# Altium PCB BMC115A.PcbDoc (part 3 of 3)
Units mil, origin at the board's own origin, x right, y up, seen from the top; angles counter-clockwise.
Board outline 5500 x 3200 mil, 4 copper layers (Top Layer, Signal Layer 1, Signal Layer 2, Bottom Layer), stack 61.6 mil thick; 199 components, 81 nets, 456 pads, 1349 vias.
Unrouted connection lines stored in the file: 741.
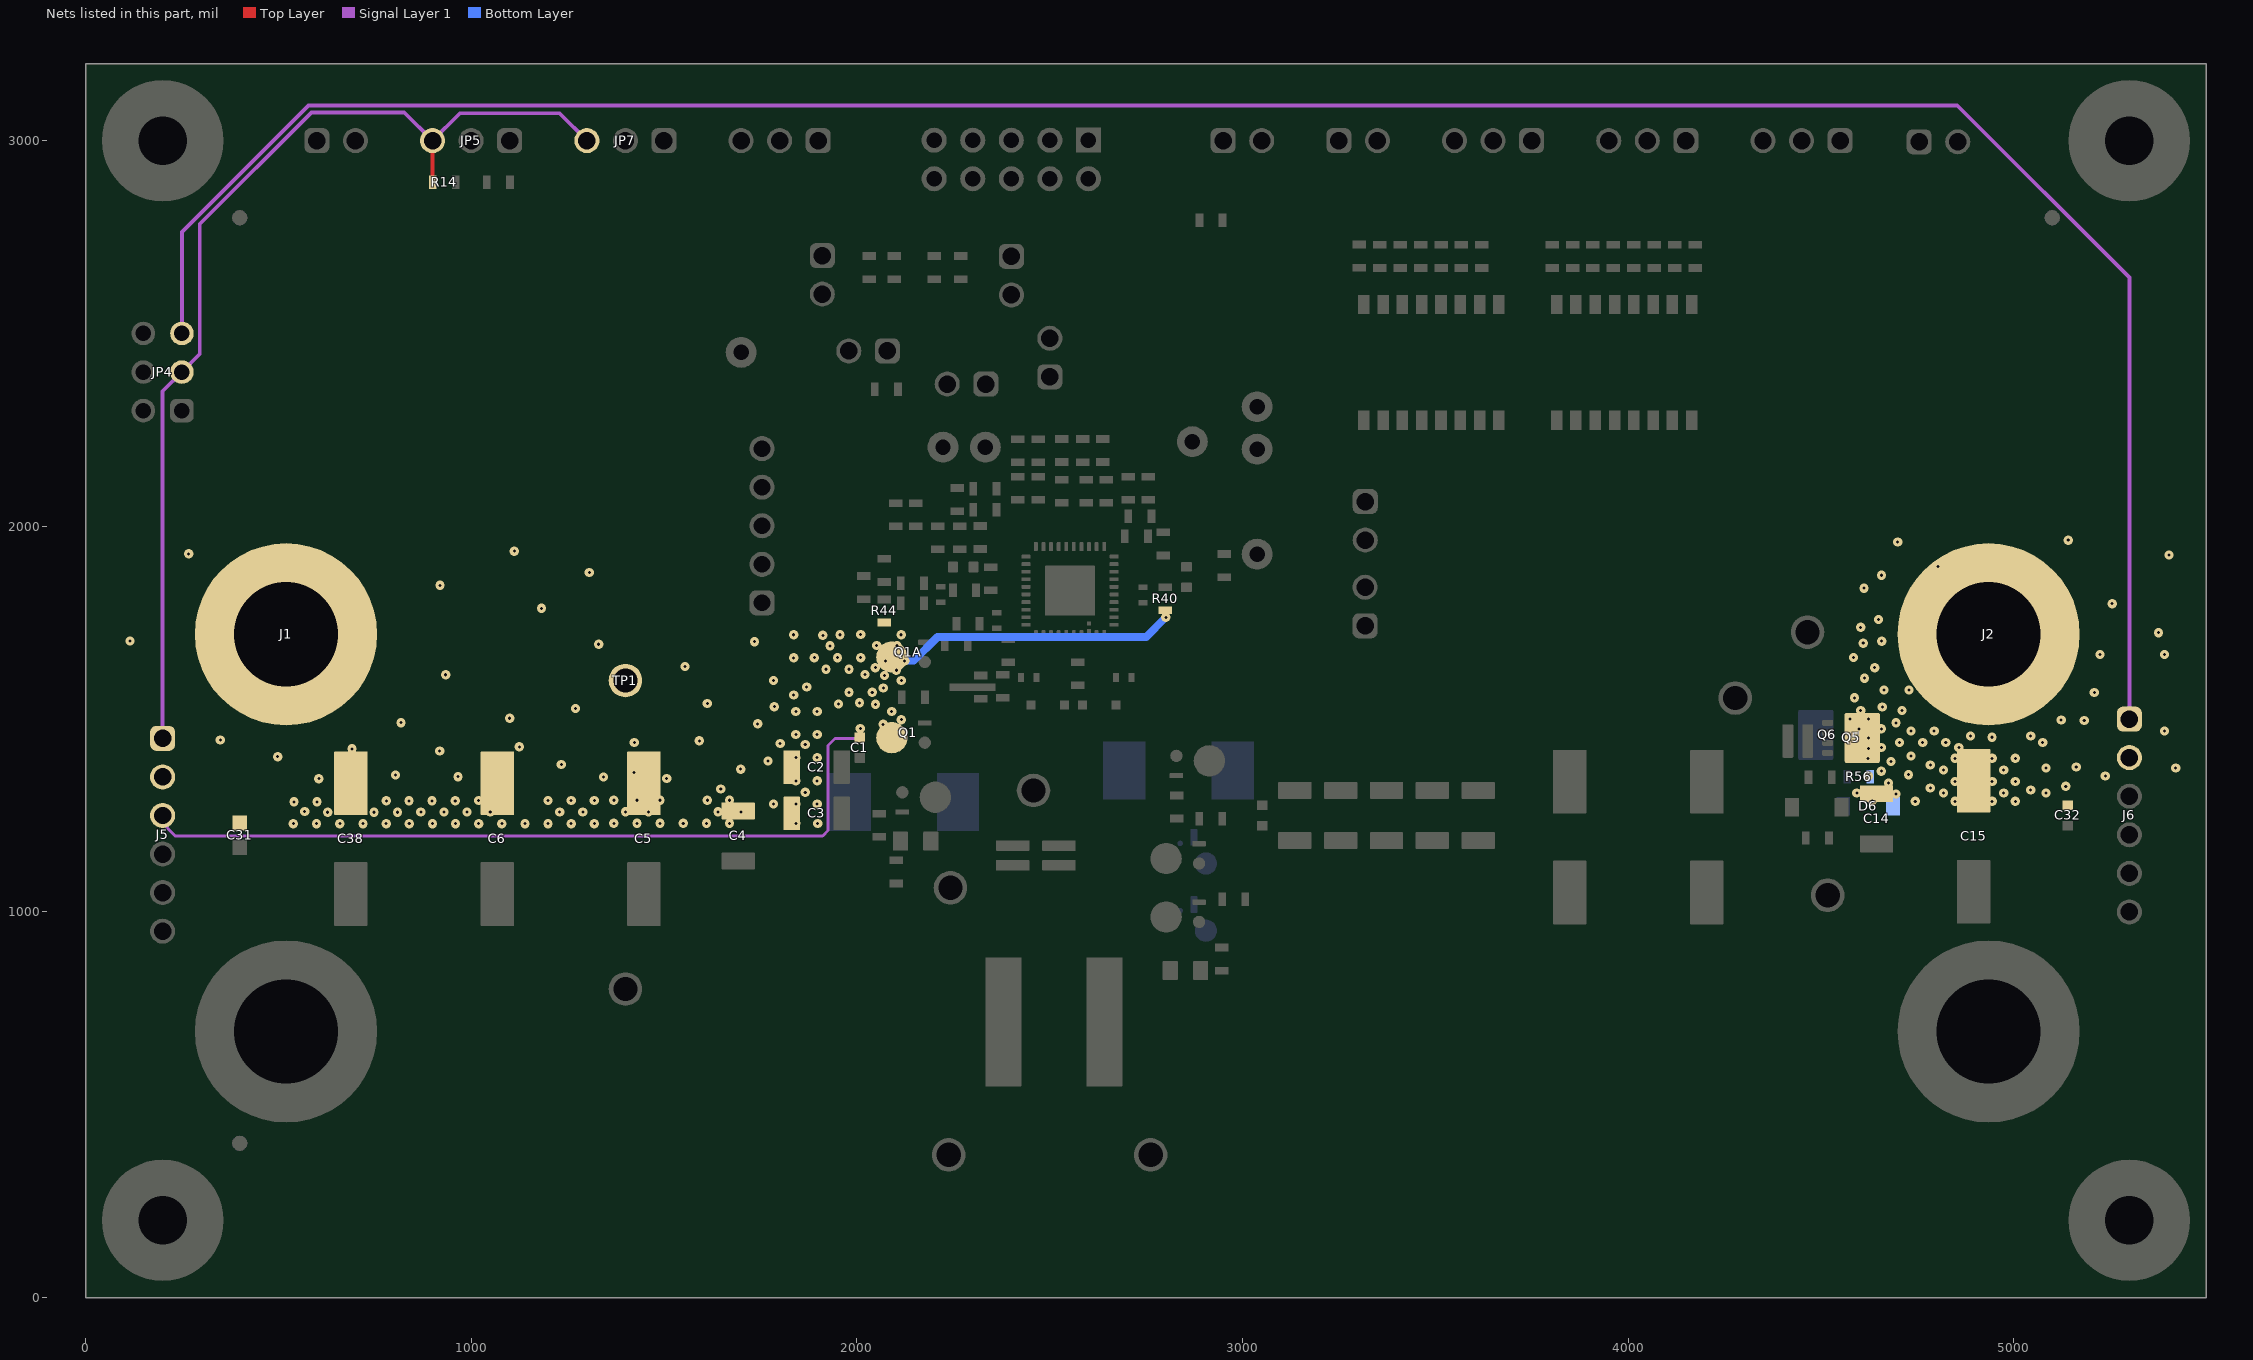
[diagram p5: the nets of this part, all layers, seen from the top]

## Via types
v1: diameter 24, hole 7.87, Top Layer to Bottom Layer, tented both sides, 1320 vias
v2: diameter 19.68, hole 7.87, Top Layer to Bottom Layer, tented both sides, 17 vias
v3: diameter 24, hole 8, Top Layer to Bottom Layer, tented both sides, 8 vias
v4: diameter 34, hole 16, Top Layer to Bottom Layer, tented both sides, 2 vias
v5: diameter 19.68, hole 7.87, Top Layer to Bottom Layer, 2 vias

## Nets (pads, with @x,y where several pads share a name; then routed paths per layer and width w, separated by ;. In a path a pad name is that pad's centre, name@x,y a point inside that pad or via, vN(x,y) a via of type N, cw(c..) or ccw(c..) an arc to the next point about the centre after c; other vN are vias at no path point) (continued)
VIN: C1.1 C2.2 C3.2 C4.2 C5.2 C6.2 C31.1 C38.2 J1.1 J5.1 J5.2 J5.3 JP4.3 JP5.3 JP7.3 Q1.5-6-7-8 Q1A.5-6-7-8 R14.2 R40.2 R44.2 TP1.1 | length 5538.3
  Top Layer w10: JP5.3@900,3005.59 JP5.3@900,3000 900,2893.04 R14.2@900.36,2892.68
  Top Layer w20: v1(2801.36,1763.92) R40.2@2801.36,1780.84
  Signal Layer 1 w8: J5.3@200,1250 210.9,1239.1 210.9,1218.72 232.76,1196.85 1911.42,1196.85 1925.49,1210.92 1925.49,1431.52 1943.54,1449.57 2000.24,1449.57 2009.24,1458.57 v1(2009.24,1475.56)
  Signal Layer 1 w10: J5.1@200,1450 200,2350 JP4.3@250,2400 296.3,2446.3 296.3,2784.02 585.7,3073.42 826.58,3073.42 JP5.3@900,3000 971,3071 1229,3071 JP7.3@1300,3000
  Bottom Layer w20: v1(2124.31,1651.11) 2147.45,1651.11 2209.26,1712.92 2750.36,1712.92 v1(2801.36,1763.92)
  other v1: 538.88,1228.76 598.88,1228.76 659.51,1228.82 719.51,1228.82 779.51,1228.82 839.51,1228.82 899.51,1228.82 959.51,1228.82 1019.51,1228.82 1079.51,1228.82 1139.51,1228.82 1199.51,1228.82 1259.51,1228.82 1319.51,1228.82 1898.5,1229.03 1370,1229.59 1430,1229.59 1490,1229.59 1550,1229.59 1610,1229.59 1670,1229.59 1842,1229.59 628,1258.41 748,1258.41 808.88,1258.41 869.51,1258.82 929.51,1258.82 989.51,1258.82 1049.51,1258.82 1229.51,1258.82 1289.51,1258.82 568.41,1260.06 1400,1259.59 1460,1259.59 1640,1259.59 1700,1259.59 1784.04,1279.83 1842,1280 1897.43,1280 540.52,1285.59 600.52,1285.59 780,1288.06 838.76,1288.06 898.76,1288.06 958.76,1288.06 1019.51,1288.82 1199.51,1288.82 1259.51,1288.82 1319.51,1288.82 1370,1289.59 1430,1289.59 1490,1289.59 1612.36,1289.59 1670,1289.59 1866.34,1310 1647.21,1318.56 1842,1340 1897.43,1340 605.03,1345.35 1506.95,1346.21 1343.23,1349.82 966.06,1350.65 803.82,1354.77 1422.29,1361.35 1698.84,1370.19 1233.7,1381.94 1770.06,1391.21 1842,1400 1897.43,1400 498.29,1402.53 918.29,1417.35 690.73,1423 1125,1428.01 1866.34,1433.99 1801.3,1436.99 1423,1439 1591.7,1443.77 349.48,1445.59 1842,1460 1897.43,1460 2068.5,1486.3 1743.1,1487.65 817.82,1490.65 2115.51,1498.5 1100,1502.14 1842,1520 1897.43,1520 2090.43,1520 1270.29,1527.67 1786.21,1532.2 2048.86,1538.33 1952.58,1539.19 1612.36,1540.58 2006.85,1542.3 1836.26,1562.63 1980,1569.29 2040.08,1569.29 2068.84,1580.32 1870.04,1583.07 1784,1600 2115.51,1599.81 2072,1613.3 933.99,1615.02 2021.58,1615.5 2102.52,1626.63 1919.92,1629.29 1980,1629.29 2048.17,1633.47 1554.27,1636.1 2075,1651.11 1836.26,1658.82 1889.92,1659.18 1949.92,1659.18 2010.08,1659.29 1930.38,1690.1 2051.61,1691.14 2104,1691.14 1330.73,1694.08 1734.98,1700.64 115.11,1702.55 1911.91,1717.12 1836.26,1718.71 1956.34,1718.71 2010.08,1719.18 2115.16,1718.71 1182.48,1787.26 919.37,1846.89 1306.43,1880.07 267.59,1928.45 1111.89,1935.51
VOUT: C14.2 C15.2 C32.1 D6.1 J2.1 J6.1 J6.2 JP4.5 Q5.5 Q5.6 Q5.7 Q5.8 Q5.9@4607.35,1451.29 Q6.1 Q6.2 Q6.3 R56.2 | length 6778.8
  Signal Layer 1 w10: JP4.5@250,2500 250,2763 578.29,3091.29 585.32,3091.29 4853.71,3091.29 5300,2645 J6.1@5300,1500
  other v1: 4744.85,1286.72 4847.88,1286.67 4944.18,1286.67 5004.18,1286.67 4633.32,1288.18 4694.85,1305.64 4593.3,1308.36 4817.88,1308.21 4974.18,1308.21 5083.7,1308.26 5044.12,1316.12 4783.94,1321.04 5135.1,1325.73 4675.58,1334.21 4847.88,1338.21 4944.18,1338.21 5004.18,1338.21 4623.37,1352.74 5237.61,1352.74 4727.12,1355.72 4656.87,1364.86 4817.88,1368.21 4974.18,1368.21 5083.77,1373 5420,1373 5162.3,1375.65 4783.94,1381.04 4681.99,1390.31 4622.46,1397.99 4847.88,1398.21 4944.18,1398.21 5004.18,1398.21 4733.62,1404.06 4623.22,1424.1 4656.87,1426.26 4857.88,1426.21 4703.94,1439.04 4763.94,1439.04 4823.94,1439.04 5075.16,1439.29 4623.29,1451.29 4944.12,1452.9 4887.88,1456.21 5044.18,1456.21 4733.94,1469.04 4793.94,1469.04 5391.07,1469.06 4599.21,1474.72 4656.93,1474.77 4694.78,1490.34 5123.25,1497.4 5183.02,1496.53 4575.58,1499.66 4623.22,1499.66 4710.19,1522.15 4603.21,1522.59 4659.33,1531.34 4587.27,1555.24 5209.27,1568.76 4663.88,1575.64 4728.28,1575.64 4612.93,1606.05 4639.52,1633.46 4584.92,1659.49 5223.98,1667.4 5391.07,1667.4 4610,1697 4657.75,1702.06 5375.43,1724.17 4603.27,1737.89 4649.27,1758.45 5255.57,1799.17 4612.04,1839.51 4657,1873 4803.96,1895.1 5402.75,1925.61 4699.22,1959.15 5141.56,1963.96
pads on no net: FID1.1 FID2.1 FID3.1 FID4.1 FID5.1 FID6.1 H1.1 H2.1 H3.1 H4.1 H5.0 H6.0 H7.0 H8.0 J12.1 J12.2 J12.3 J12.4 J12.7 J12.8 Q5.9@4570.34,1390.26 Q5.9@4570.34,1451.29 Q5.9@4570.34,1512.31 Q5.9@4593.37,1428.84 Q5.9@4593.37,1473.73 Q5.9@4599.27,1451.29 Q6.9@4494.94,1459.16 Q6.9@4500.85,1436.72 Q6.9@4500.85,1481.6 Q6.9@4523.88,1398.14 Q6.9@4523.88,1459.16 Q6.9@4523.88,1520.18 U1.26 U1.34 U1.39
copper on no net:
  other v1: 2932.87,647.32 2838.08,684.89 3019.82,1188.25

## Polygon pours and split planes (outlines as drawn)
VOUT on Top Layer "TOP_LAYER_VOUT_P119" (solid, pour order 119): 4554.57,1891.03 4554.57,1255 5500,1255 5500,2004 4667.53,2004
NetD5_1 on Top Layer "TOP_LAYER_NETD5_1_P022" (solid, remove dead copper, pour order 22): 4416.18,1746.69 4416.18,1567.14 4444.84,1538.48 4444.84,1334.16 4456.77,1322.23 4481.07,1322.23 4492.49,1333.65 4492.49,1424.3 4497.82,1429.63 4530.65,1429.63 4541.14,1440.12 4541.14,1738.55 4500.7,1778.99 4448.49,1778.99
NetC7_1 on Top Layer "TOP_LAYER_NETC7_1_P120" (solid, pour order 120): 3045.12,1255.01 4428.19,1255 4428.19,1633.46 2871.23,1633.46 ccw(c2871.23,1625.22) 2863,1625.22 2863,1283.2 ccw(c2876.2,1283.2) 2876.2,1270 3008.91,1270 cw(c3008.92,1249.19) 3023.64,1263.9 ccw(c3045.1,1285.37)
GND on Top Layer "TOP_LAYER_GND_P087" (solid, pour order 87): 0,0 5500,0 5500,1238.93 2870,1238.93 2870,309.85 cw(c2835.02,309.84) 2835.01,274.86 2607.14,274.86 cw(c2607.14,297.66) 2584.35,297.66 2584.35,959.2 ccw(c2568.55,959.2) 2568.55,975 2441.33,975 ccw(c2441.32,957.51) 2423.84,957.5 2423.84,294.72 cw(c2404.12,294.72) 2404.11,275 2173.69,275 cw(c2173.69,303.23) 2145.45,303.24 2145.45,1366.8 ccw(c2121.81,1374.65) 2127.82,1398.83 2032.56,1399.14 2011.3,1424.81 1922.11,1424.81 1922.11,1207.54 cw(c1913.77,1207.53) 1913.75,1199.19 0,1199.19
NetL1_1 on Top Layer "TOP_LAYER_NETL1_1_P021" (solid, pour order 21): 2436.39,989.69 2574.16,989.69 ccw(c2574.16,999.87) 2584.35,999.87 2584.35,1137.65 ccw(c2576.82,1137.65) 2576.82,1145.17 2161.23,1145.43 2161.23,300.08 ccw(c2173.85,300.08) 2173.85,287.46 2426.5,287.46 2426.5,979.8 cw(c2436.39,979.8)
NetC22_2 on Top Layer "TOP_LAYER_NETC22_2_P071" (solid, remove dead copper, pour order 71): 2156.9,1156.72 2156.9,1222.85 2156.9,1680.02 2281.89,1680.02 2291.77,1670.14 2291.77,1479.93 ccw(c2321.7,1479.93) 2321.7,1450 2564.78,1450 cw(c2564.78,1429.72) 2585.06,1429.72 2585.06,1165.83 cw(c2575.94,1165.83) 2575.94,1156.72
SW2 on Top Layer "TOP_LAYER_SW2_P019" (solid, pour order 19): 2594.54,1448.03 2849.53,1447.5 2849.53,303.65 cw(c2833.35,303.64) 2833.35,287.46 2594.54,287.46
VIN on Top Layer "TOP_LAYER_VIN_P067" (solid, pour order 67): 1910.08,1217.96 1910.08,1431.52 2012.71,1431.52 2035.07,1406.76 2135.48,1405.05 2135.6,1431.52 2136.96,1753.68 1630.45,1755.5 1374.95,2011 0,2011 0,1210.36 1902.48,1210.36 ccw(c1902.48,1217.96)
AGND on Top Layer "TOP_LAYER_AGND_P105" (solid, pour order 105): -12.05,2030.48 1363.72,2030.48 1621.68,1772.52 2347.34,1772.52 2349.08,1649.19 4281.61,1649.19 4651.83,2019.44 5487.95,2019.44 5487.95,3200.48 -12.05,3200.48
GND on Top Layer "TOP_LAYER_GND_P116" (solid, remove dead copper, pour order 116): 2411.18,1470.43 2849.33,1470.43 2849.33,1686.44 2401.09,1686.44 2399.47,1482.24 ccw(c2411.18,1482.15)
GND on Signal Layer 1 "SIGNAL_LAYER_1_GND_P098" (solid, pour order 98): 1956.34,1406.83 1976.39,1426.87 2123.24,1426.69 2145.45,1404.46 2145.45,1152.69 ccw(c2152.84,1152.69) 2152.84,1145.3 2597.32,1145.3 cw(c2597.32,1135.11) 2607.5,1135.11 2607.5,300.57 ccw(c2633.21,300.57) 2633.22,274.86 2835,274.86 ccw(c2835.01,309.84) 2870,309.85 2870,1235.97 cw(c2886.53,1235.97) 2886.53,1252.5 3075.17,1252.5 3082.67,1245 5500,1245 5500,0 0,0 0,1164.45 1932.65,1164.45 ccw(c1932.66,1188.14) 1956.34,1188.15
AGND on Signal Layer 1 "SIGNAL_LAYER_1_AGND_P106" (solid, remove dead copper, pour order 106): -3.94,2029.67 1379.83,2029.67 1710.87,1698.63 4342.97,1698.63 4662.95,2018.63 5496.06,2018.63 5496.06,3199.67 -3.94,3199.67
VIN on Signal Layer 1 "SIGNAL_LAYER_1_VIN_P100" (solid, pour order 100): 1909.59,1221.92 1909.59,1431.52 2120.08,1431.52 ccw(c2120.08,1446.6) 2135.15,1446.53 2136.27,1711.33 ccw(c2105.01,1711.46) 2105.12,1742.73 1645.04,1744.38 1374.46,2014.96 -0.49,2014.96 -0.49,1214.32 1901.99,1214.32 ccw(c1901.99,1221.92)
NetC22_2 on Signal Layer 1 "SIGNAL_LAYER_1_NETC22_2_P117" (solid, remove dead copper, pour order 117): 2156.9,1169.43 2156.9,1222.85 2156.9,1620 2278.38,1620 2291.77,1606.61 2291.77,1479.93 ccw(c2321.7,1479.93) 2321.7,1450 2584.35,1450 cw(c2584.35,1426.99) 2607.36,1426.98 2607.36,1156.72 2169.6,1156.72 cw(c2169.6,1169.43)
NetC7_1 on Signal Layer 1 "SIGNAL_LAYER_1_NETC7_1_P072" (solid, pour order 72): 2884.91,1272.33 4433.64,1272.33 4433.64,1633.46 2873.87,1633.46 2873.87,1283.37 ccw(c2884.91,1283.37)
SW2 on Signal Layer 1 "SIGNAL_LAYER_1_SW2_P094" (solid, pour order 94): 2636.76,1448.03 2802.07,1448.03 cw(c2802.07,1427.89) 2822.22,1427.89 2822.22,1113.65 ccw(c2847.39,1113.65) 2829.59,1095.85 2839.32,1086.12 cw(c2812.48,1059.29) 2850.44,1059.24 2849.53,303.64 cw(c2833.35,303.64) 2833.35,287.46 2636.56,287.46 cw(c2636.56,305.8) 2618.22,305.81 2618.22,1429.49 cw(c2636.76,1429.49)
VOUT on Signal Layer 1 "SIGNAL_LAYER_1_VOUT_P103" (solid, pour order 103): 4444.84,1781.31 4444.84,1271 5500,1271 5500,2004 4667.53,2004
GND on Signal Layer 1 "SIGNAL_LAYER_1_GND_P114" (solid, remove dead copper, pour order 114): 2281.04,1471.02 2842.03,1471.02 2842.03,1695.82 2281.04,1695.82
GND on Bottom Layer "BOTTOM_LAYER_GND_P108" (solid, pour order 108): 0,0 5500,0 5500,1239.37 3031.97,1239.37 cw(c3031.97,1274.33) 3012.75,1245.12 ccw(c2988.11,1207.67) 2988.11,1252.5 2887.9,1252.5 ccw(c2887.9,1234.6) 2870,1234.6 2870,309.85 cw(c2835.01,309.85) 2835.01,274.86 2633.22,274.86 cw(c2633.22,300.57) 2607.5,300.58 2607.5,957.76 ccw(c2590.27,957.76) 2590.26,975 2441.33,975 ccw(c2441.33,957.51) 2423.84,957.5 2423.84,294.72 cw(c2404.11,294.72) 2404.11,275 2173.69,275 cw(c2173.69,303.24) 2145.45,303.24 2145.45,1438.71 ccw(c2134.16,1438.71) 2134.16,1450 1927.6,1450 ccw(c1927.6,1444.5) 1922.11,1444.5 1922.11,1207.54 cw(c1913.76,1207.53) 1913.75,1199.19 0,1199.19
VIN on Bottom Layer "BOTTOM_LAYER_VIN_P093" (solid, pour order 93): 1910.08,1210.36 1910.08,1448.79 cw(c1916.95,1448.79) 1916.95,1455.66 2128.02,1455.66 ccw(c2128.02,1463.38) 2135.73,1463.35 2136.91,1741.91 1646.59,1741.91 1369.83,2018.67 0,2019.95 0,1210.36
NetD5_1 on Bottom Layer "BOTTOM_LAYER_NETD5_1_P062" (solid, remove dead copper, pour order 62): 4416.18,1746.69 4416.18,1567.14 4444.84,1538.48 4444.84,1334.16 4456.77,1322.23 4481.07,1322.23 4492.49,1333.65 4492.49,1424.3 4497.82,1429.63 4530.65,1429.63 4541.14,1440.12 4541.14,1738.55 4500.7,1778.99 4448.49,1778.99
VOUT on Bottom Layer "BOTTOM_LAYER_VOUT_P122" (solid, pour order 122): 4444,1787.53 4444,1257.92 5500,1257.92 5500,2004 4660.47,2004
NetC22_2 on Bottom Layer "BOTTOM_LAYER_NETC22_2_P121" (solid, remove dead copper, pour order 121): 2156.9,1156.72 2156.9,1222.85 2156.9,1609.94 cw(c2166.96,1609.94) 2166.96,1620 2272.05,1620 2291.77,1600.28 2291.77,1479.93 ccw(c2321.7,1479.93) 2321.7,1450 2584.35,1450 cw(c2584.35,1426.99) 2607.36,1426.98 2607.36,1171.08 cw(c2593,1171.08) 2593,1156.72
NetC7_1 on Bottom Layer "BOTTOM_LAYER_NETC7_1_P078" (solid, pour order 78): 3042.41,1255 4433.64,1255 4433.64,1633.46 2881.88,1633.46 ccw(c2881.88,1621.57) 2870,1621.57 2870,1294.23 ccw(c2894.23,1294.23) 2894.23,1270 3006.2,1270 cw(c3006.2,1250.57) 3019.94,1264.31 ccw(c3042.41,1286.78)
NetL1_1 on Bottom Layer "BOTTOM_LAYER_NETL1_1_P095" (solid, pour order 95): 2439.03,989.69 2595.02,989.69 ccw(c2595.03,1002.17) 2607.5,1002.17 2607.5,1134.72 ccw(c2595.78,1134.72) 2595.78,1146.45 2210.26,1146.68 ccw(c2210.25,1124.89) 2188.51,1123.26 ccw(c2184.99,1098.44) 2161.23,1106.44 2161.23,300.08 ccw(c2173.85,300.08) 2173.85,287.46 2396.66,287.46 ccw(c2396.66,300.53) 2409.73,300.53 2409.73,960.4 cw(c2439.03,960.4)
SW2 on Bottom Layer "BOTTOM_LAYER_SW2_P099" (solid, pour order 99): 2636.76,1448.03 2832.96,1448.03 cw(c2832.96,1431.46) 2849.53,1431.46 2849.53,303.65 cw(c2833.35,303.64) 2833.35,287.46 2636.56,287.46 cw(c2636.56,305.81) 2618.22,305.81 2618.22,1429.49 cw(c2636.76,1429.49)
GND on Bottom Layer "BOTTOM_LAYER_GND_P113" (solid, remove dead copper, pour order 113): 2289.97,1471.02 2837.53,1471.02 ccw(c2837.53,1490.05) 2856.56,1490.05 2856.56,1690.6 2289.97,1690.6
AGND on Bottom Layer "BOTTOM_LAYER_AGND_P115" (solid, pour order 115): -3.94,2029.67 1375.2,2029.67 1752.3,1652.58 2994.42,1652.99 4292.24,1652.99 4657.85,2018.63 5496.06,2018.63 5496.06,3199.67 -3.94,3199.67
GND on Signal Layer 2 "SIGNAL_LAYER_2_GND_P112" (solid, pour order 112): 38,27 5458,27 ccw(c5458,44) 5475,44 5475,2003.06 4671.42,2003.06 4385.48,1717.12 1675.68,1717.12 1373.24,2019.31 25.49,2019.31 25.49,39.51 ccw(c38,39.51)
VIN on Signal Layer 2 "SIGNAL_LAYER_2_VIN_P111" (solid, pour order 111): 1910.08,1217.96 1910.08,1411.13 cw(c1930.47,1411.13) 1930.47,1431.52 2124.54,1431.52 ccw(c2124.54,1442.62) 2135.64,1442.58 2136.83,1724.06 ccw(c2122.24,1724.12) 2122.3,1738.71 1645.53,1740.42 1374.95,2011 45,2011 ccw(c45,1991.49) 25.49,1991.49 25.49,1210.36 1902.48,1210.36 ccw(c1902.48,1217.96)
NetC7_1 on Signal Layer 2 "SIGNAL_LAYER_2_NETC7_1_P024" (solid, pour order 24): 2915.49,1268.5 4413.7,1270.32 ccw(c4413.67,1290.17) 4433.52,1290.17 4433.52,1622.62 ccw(c4419.17,1622.62) 4419.17,1636.97 2883.88,1636.96 ccw(c2883.87,1623.09) 2870,1623.09 2870,1313.99
VOUT on Signal Layer 2 "SIGNAL_LAYER_2_VOUT_P035" (solid, pour order 35): 4554.57,1891.03 4554.57,1255 5500,1255 5500,2004 4667.53,2004
AGND on Signal Layer 2 "SIGNAL_LAYER_2_AGND_P118" (solid, pour order 118): 41.33,2029.67 1388.26,2029.67 1690.02,1727.9 4375.57,1728.79 4665.38,2018.63 5475,2018.63 5475,3162 ccw(c5463,3162) 5463,3174 38,3174 ccw(c38,3162) 26,3162 26,2045 ccw(c41.33,2045)

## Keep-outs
Keep-Out Layer:
  text ".Layer_Name" at 577,-858.49 h60

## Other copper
Top Layer:
  pour cut-out: 158.17,1249.67 cw(c199.52,1249.67) 199.52,1291.03 cw(c199.52,1249.67) 240.87,1249.67 cw(c199.52,1249.67) 199.52,1208.32 cw(c199.52,1249.67)
  pour cut-out: 5258.88,1300.24 cw(c5300.24,1300.24) 5300.24,1341.59 cw(c5300.24,1300.24) 5341.59,1300.24 cw(c5300.24,1300.24) 5300.24,1258.89 cw(c5300.24,1300.24)
  pour cut-out: 5258.4,1199.72 cw(c5299.75,1199.72) 5299.75,1241.07 cw(c5299.75,1199.72) 5341.11,1199.72 cw(c5299.75,1199.72) 5299.75,1158.37 cw(c5299.75,1199.72)
  pour cut-out: 158.75,1150.28 cw(c200.1,1150.28) 200.1,1191.63 cw(c200.1,1150.28) 241.46,1150.28 cw(c200.1,1150.28) 200.1,1108.93 cw(c200.1,1150.28)
  pour cut-out: 2127.82,1214.45 2127.99,1214.62 2145.52,1214.62 2145.52,1215.84 2144.61,1216.75 2128.18,1216.75
  text ".Layer_Name" at 577,-858.49 h60
Signal Layer 1:
  pour cut-out: 1987.95,1391.93 cw(c2009.46,1391.93) 2009.46,1413.44 cw(c2009.46,1391.93) 2030.97,1391.93 cw(c2009.46,1391.93) 2009.46,1370.42 cw(c2009.46,1391.93)
  pour cut-out: 3028.91,1295.45 cw(c3050.42,1295.45) 3050.42,1316.95 cw(c3050.42,1295.45) 3071.93,1295.45 cw(c3050.42,1295.45) 3050.42,1273.94 cw(c3050.42,1295.45)
  pour cut-out: 158.17,1249.67 cw(c199.52,1249.67) 199.52,1291.03 cw(c199.52,1249.67) 240.87,1249.67 cw(c199.52,1249.67) 199.52,1208.32 cw(c199.52,1249.67)
  pour cut-out: 158.75,1150.28 cw(c200.1,1150.28) 200.1,1191.63 cw(c200.1,1150.28) 241.46,1150.28 cw(c200.1,1150.28) 200.1,1108.93 cw(c200.1,1150.28)
  pour cut-out: 1986.65,1476.89 cw(c2008.15,1476.89) 2008.15,1498.4 cw(c2008.15,1476.89) 2029.66,1476.89 cw(c2008.15,1476.89) 2008.15,1455.38 cw(c2008.15,1476.89)
  pour cut-out: 3030.11,1205.46 cw(c3051.62,1205.46) 3051.62,1226.96 cw(c3051.62,1205.46) 3073.12,1205.46 cw(c3051.62,1205.46) 3051.62,1183.95 cw(c3051.62,1205.46)
  pour cut-out: 4393.28,1492.55 cw(c4414.78,1492.55) 4414.78,1514.06 cw(c4414.78,1492.55) 4436.29,1492.55 cw(c4414.78,1492.55) 4414.78,1471.04 cw(c4414.78,1492.55)
  pour cut-out: 4444.08,1493.24 cw(c4465.59,1493.24) 4465.59,1514.75 cw(c4465.59,1493.24) 4487.1,1493.24 cw(c4465.59,1493.24) 4465.59,1471.74 cw(c4465.59,1493.24)
  pour cut-out: 5258.88,1300.24 cw(c5300.24,1300.24) 5300.24,1341.59 cw(c5300.24,1300.24) 5341.59,1300.24 cw(c5300.24,1300.24) 5300.24,1258.89 cw(c5300.24,1300.24)
  pour cut-out: 5258.4,1199.72 cw(c5299.75,1199.72) 5299.75,1241.07 cw(c5299.75,1199.72) 5341.11,1199.72 cw(c5299.75,1199.72) 5299.75,1158.37 cw(c5299.75,1199.72)
  pour cut-out: 1916.58,1461.68 2023.36,1461.68 2023.36,1410.43 1910.08,1410.43 1910.08,1455.18
  pour cut-out: 4480.06,1491.95 4480.88,1492.77 4480.88,1516.89 4468.7,1529.08 4468.7,1558.82 4430.88,1596.64 4430.88,1555.81 4438.71,1547.98 4438.71,1514.49 4467.25,1485.95 4469.35,1485.95
  pour cut-out: 3074.04,1195.17 3106.87,1228 5253.06,1228 5277.26,1203.79 5296.16,1222.7 5298.2,1222.7 5298.2,1223.58 5263.86,1257.92 3076.63,1257.92 3049.48,1230.76 3049.48,1207.09
  text ".Layer_Name" at 577.07,-859.59 h60
Signal Layer 2:
  pour cut-out: 3028.91,1295.45 cw(c3050.42,1295.45) 3050.42,1316.95 cw(c3050.42,1295.45) 3071.93,1295.45 cw(c3050.42,1295.45) 3050.42,1273.94 cw(c3050.42,1295.45)
  pour cut-out: 4394.28,1492.55 cw(c4415.78,1492.55) 4415.78,1514.06 cw(c4415.78,1492.55) 4437.29,1492.55 cw(c4415.78,1492.55) 4415.78,1471.04 cw(c4415.78,1492.55)
  pour cut-out: 1986.65,1476.89 cw(c2008.15,1476.89) 2008.15,1498.4 cw(c2008.15,1476.89) 2029.66,1476.89 cw(c2008.15,1476.89) 2008.15,1455.38 cw(c2008.15,1476.89)
  pour cut-out: 158.17,1249.67 cw(c199.52,1249.67) 199.52,1291.03 cw(c199.52,1249.67) 240.87,1249.67 cw(c199.52,1249.67) 199.52,1208.32 cw(c199.52,1249.67)
  pour cut-out: 158.75,1150.28 cw(c200.1,1150.28) 200.1,1191.63 cw(c200.1,1150.28) 241.46,1150.28 cw(c200.1,1150.28) 200.1,1108.93 cw(c200.1,1150.28)
  pour cut-out: 1986.54,1391.02 cw(c2008.05,1391.02) 2008.05,1412.53 cw(c2008.05,1391.02) 2029.56,1391.02 cw(c2008.05,1391.02) 2008.05,1369.51 cw(c2008.05,1391.02)
  pour cut-out: 5258.88,1300.24 cw(c5300.24,1300.24) 5300.24,1341.59 cw(c5300.24,1300.24) 5341.59,1300.24 cw(c5300.24,1300.24) 5300.24,1258.89 cw(c5300.24,1300.24)
  pour cut-out: 5258.4,1199.72 cw(c5299.75,1199.72) 5299.75,1241.07 cw(c5299.75,1199.72) 5341.11,1199.72 cw(c5299.75,1199.72) 5299.75,1158.37 cw(c5299.75,1199.72)
  pour cut-out: 3029.67,1203.63 cw(c3051.18,1203.63) 3051.18,1225.14 cw(c3051.18,1203.63) 3072.69,1203.63 cw(c3051.18,1203.63) 3051.18,1182.13 cw(c3051.18,1203.63)
  pour cut-out: 4415.78,1514.06 4416.73,1515 4460.92,1515 4460.92,1471 4460.87,1471.04 4415.78,1471.04
  text ".Layer_Name" at 575.75,-859.59 h60
Bottom Layer:
  pour cut-out: 3028.91,1295.45 cw(c3050.42,1295.45) 3050.42,1316.95 cw(c3050.42,1295.45) 3071.93,1295.45 cw(c3050.42,1295.45) 3050.42,1273.94 cw(c3050.42,1295.45)
  pour cut-out: 1986.65,1476.89 cw(c2008.15,1476.89) 2008.15,1498.4 cw(c2008.15,1476.89) 2029.66,1476.89 cw(c2008.15,1476.89) 2008.15,1455.38 cw(c2008.15,1476.89)
  pour cut-out: 158.17,1249.67 cw(c199.52,1249.67) 199.52,1291.03 cw(c199.52,1249.67) 240.87,1249.67 cw(c199.52,1249.67) 199.52,1208.32 cw(c199.52,1249.67)
  pour cut-out: 158.75,1150.28 cw(c200.1,1150.28) 200.1,1191.63 cw(c200.1,1150.28) 241.46,1150.28 cw(c200.1,1150.28) 200.1,1108.93 cw(c200.1,1150.28)
  pour cut-out: 1987.95,1391.93 cw(c2009.46,1391.93) 2009.46,1413.44 cw(c2009.46,1391.93) 2030.97,1391.93 cw(c2009.46,1391.93) 2009.46,1370.42 cw(c2009.46,1391.93)
  pour cut-out: 3029.67,1205.31 cw(c3051.18,1205.31) 3051.18,1226.82 cw(c3051.18,1205.31) 3072.68,1205.31 cw(c3051.18,1205.31) 3051.18,1183.8 cw(c3051.18,1205.31)
  pour cut-out: 4394.27,1493 cw(c4415.77,1493) 4415.77,1514.51 cw(c4415.77,1493) 4437.28,1493 cw(c4415.77,1493) 4415.77,1471.49 cw(c4415.77,1493)
  pour cut-out: 4443.94,1492.91 cw(c4465.45,1492.91) 4465.45,1514.41 cw(c4465.45,1492.91) 4486.96,1492.91 cw(c4465.45,1492.91) 4465.45,1471.4 cw(c4465.45,1492.91)
  pour cut-out: 5258.4,1199.72 cw(c5299.75,1199.72) 5299.75,1241.07 cw(c5299.75,1199.72) 5341.11,1199.72 cw(c5299.75,1199.72) 5299.75,1158.37 cw(c5299.75,1199.72)
  pour cut-out: 5258.88,1300.24 cw(c5300.24,1300.24) 5300.24,1341.59 cw(c5300.24,1300.24) 5341.59,1300.24 cw(c5300.24,1300.24) 5300.24,1258.89 cw(c5300.24,1300.24)
  text ".Layer_Name" at 577,-858.49 h60

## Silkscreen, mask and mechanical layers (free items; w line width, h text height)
Top Overlay:
  lines w6: 1991.97,2190.64 2143.27,2190.64 2205.19,2128.72 2272.36,2128.72 2280,2121.08 ; 2182.41,1925.12 2187.12,1920.42 2262.16,1920.42 2268.78,1913.8 ; 2190.87,1777.37 2201.71,1788.22 ; 2228.42,1876.39 2233.85,1870.96 2233.85,1870.7 2264.21,1870.7 2264.3,1870.42 2264.67,1870.42 2278,1857.08
  text "FLT" at 2962.38,2843.67 h35 r90
  text "VIN" at 1316.8,2821.21 h35 r90
  text "AGND" at 713,2818.85 h35 r90
  text "VEXT" at 617.09,2818 h35 r90
  text "CDC" at 3259.94,2818.33 h35 r90
  text "AGND" at 3367.13,2818.33 h35 r90
  text "VCC2" at 1716.8,2815.55 h35 r90
  text "ILIM" at 1788.41,2815.55 h35 r90
  text "VCC2" at 4370.08,2816.35 h35 r90
  text "SYNC" at 4472.01,2816.35 h35 r90
  text "AGND" at 4577.05,2816.35 h35 r90
  text "VCC1" at 4776.03,2815.42 h35 r90
  text "GND" at 4875.08,2814.32 h35 r90
  text "AGND" at 3068.23,2812.16 h35 r90
  text "VCC2" at 3574.61,2811.67 h35 r90
  text "MODE" at 3669,2811.67 h35 r90
  text "AGND" at 3769.61,2811.67 h35 r90
  text "VCC2" at 3970.08,2811.67 h35 r90
  text "DTRK" at 4069,2811.67 h35 r90
  text "AGND" at 4169,2811.67 h35 r90
  text "NRST" at 1418,2809.55 h35 r90
  text "AGND" at 1516.34,2809.55 h35 r90
  text "AGND" at 1916.34,2809.55 h35 r90
  text "COMP" at 1837.29,2807.64 h35 r90
  text "VIN" at 919.98,2759.55 h35 r90
  text "AGND" at 1117.45,2721.49 h35 r90
  text "CFG3" at 2475.92,2684.91 h35
  text "CFG4" at 1727.16,2681.85 h35
  text "EN/UVLO" at 1023.7,2616.14 h35 r90
  text "AGND" at 2468.16,2589.99 h35
  text "AGND" at 1728.81,2585.15 h35
  text "VOUT" at 332.19,2487.32 h35
  text "AGND" at 2561.16,2469.78 h35
  text "AGND" at 2177.08,2427.66 h30
  text "RT" at 2322.11,2427.45 h30
  text "VIN" at 332.19,2385.55 h35
  text "SLOPE" at 2560.06,2376.48 h35
  text "VCC2" at 1629.17,2343.2 h35
  text ".PRJ_title" at 4546,2341 h60
  text "AGND" at 3111.3,2286.86 h35
  text "SYNC" at 2808.26,2285.38 h35
  text "VEXT" at 335.47,2280.89 h35
  text "AGND" at 2143.27,2275.44 h30
  text "COMP" at 2272.29,2275.44 h30
  text "'.PRJ_Number'" at 4546,2257.23 h40
  text "VCC2" at 1555.53,2190.13 h35
  text "SS/ATRK" at 3113.89,2184.75 h35
  text "REV..PCB_Rev" at 4546,2185 h40
  text "R_FB" at 1555.53,2081 h35
  text "CFG2" at 3380.61,2041.87 h35
  text "AGND" at 1555.53,1983.61 h35
  text "AGND" at 3380.61,1949.32 h35
  text "BIAS" at 3111.3,1910.76 h35
  text "AC_B" at 1555.53,1883.03 h35
  text "AGND" at 3382.59,1828.87 h35
  text "ISNSN" at 4391.39,1816 h35
  text "AC_A" at 1555.53,1783.36 h35
  text "DRV1" at 3382.59,1732.71 h35
  text "ISNSP" at 4203.57,1639.46 h35
  text "Max.5.5A" at 5193.4,1624.45 h35
  text "20V" at 5251.98,1570.94 h35
  text "Max.10A" at 61,1570 h35
  text "9-48V" at 61,1511 h35
  text "VIN" at 1350.57,1477.24 h35
  text "VOUT" at 5050.12,1425.78 h50
  text "VIN" at 272,1378 h50
  text "CSA" at 2558.02,1301 h35
  text "S+" at 5172.67,1282.57 h35
  text "S+" at 259.95,1236.68 h35
  text "S-" at 5168.3,1182.75 h35
  text "S-" at 271.64,1136.69 h35
  text "GND" at 5096.21,1019.16 h50
  text "CSB" at 2067.5,994.66 h35
  text "GND" at 275,987 h50
  text "GND" at 4470.29,918.43 h35
  text "GND" at 1356.57,660.89 h35
  text "SW2" at 2863.21,356.7 h35
  text "SW1" at 2042.3,354.85 h35
  text ".Layer_Name" at 577,-858.49 h60
Bottom Overlay:
  text ".Layer_Name" at 577,-858.49 h60
Top Paste:
  text ".Layer_Name" at 577,-858.49 h60
Bottom Paste:
  text ".Layer_Name" at 577,-858.49 h60
Top Solder:
  rectangle: 2155.04,961.22 2434.31,979.41
  rectangle: 4518.49,1537.81 4575.18,1645.98
  text ".Layer_Name" at 577,-858.49 h60
  text ".Layer_Name" at 577,-858.49 h60
Bottom Solder:
  rectangle: 2155.78,954.89 2415.07,969.95
  text ".Layer_Name" at 577,-858.49 h60
Drill Guide:
  text ".Layer_Name" at 577,-858.49 h60
M1 Board Outline:
  the board outline again, w10
  text ".Layer_Name" at 577,-858.49 h60
M2 Board Dimensions:
  rectangle: 0,-275 125,-150
  rectangle: 125,-400 500,-275
  lines w7: 0,-275 1000,-275 ; 125,-400 125,-150 ; 250,-400 250,-150 ; 500,-400 500,-150 ; 750,-400 750,-150 ; 0,-400 1000,-400 1000,-150 0,-150 0,-400
  text ".Layer_Name" at 577,-858.49 h60
M3 3D STEP Top:
  text ".Layer_Name" at 577,-858.49 h60
M4 3D STEP Bottom:
  text ".Layer_Name" at 577,-858.49 h60
Top M5 Assembly Top/M6 Assembly Bottom:
  lines w10: -292,-930.17 6308,-930.17 ; -292,-726.83 6310,-726.83 ; -292,-523.5 -292,-1133.5 3713,-1133.5 6310,-1133.5 6310,-523.5 -291.5,-523.5 -291.5,-1133.5 1284,-1133.5 ; 2173,-1133.5 2173,-523.5 ; 3440,-726.83 3440,-523.5 ; 4280,-726.83 4280,-523.5 ; 4902,-1140 4902,-937.17
  text "COMPONENTS MARKED 'DNP' SHOULD NOT BE POPULATED." at 1153.5,-318.5 h60
  text "ASSEMBLY VARIANT:" at 1153,-434 h60
  text ".VariantName" at 2189,-434 h60
  text "PCB VIEWED FROM TOP SIDE" at -228.5,-655.67 h60
  text "BOARD #:" at 2248,-655.67 h60
  text ".PRJ_Number" at 2793.5,-655.67 h60
  text "REV:" at 3638,-655.67 h60
  text ".PCB_Rev" at 3929.5,-655.67 h60
  text "SVN REV:" at 4476,-655.67 h60
  text ".VersionControl_RevNumber" at 4982,-655.67 h60
  text "TID #:" at 2248,-859 h60
  text ".TID" at 2793.5,-859 h60
  text "PLOT NAME =" at -228.5,-1064.34 h60
  text ".plot_File_Name" at 577,-1064.34 h60
  text "GENERATED    :" at 2250,-1064.34 h60
  text ".Print_Date" at 3119.5,-1064.34 h60
  text ".Print_Time" at 3848.5,-1064.34 h60
  text "TEXAS INSTRUMENTS" at 5113,-1064.34 h60
Bottom M5 Assembly Top/M6 Assembly Bottom:
  lines w10: -292.5,-727.33 6309.5,-727.33 ; -290.5,-930.67 6309.5,-930.67 ; 1115.5,-1140.5 1115.5,-937.67 ; 1737.5,-727.33 1737.5,-524 ; 2577.5,-727.33 2577.5,-524 ; 3844.5,-1134 3844.5,-524 ; 4733.5,-1134 6309,-1134 6309,-524 -292.5,-524 -292.5,-1134 2304.5,-1134 6309.5,-1134 6309.5,-524
  text "COMPONENTS MARKED 'DNP' SHOULD NOT BE POPULATED." at 6102,-318 h60
  text ".VariantName" at 5058,-434 h60
  text "ASSEMBLY VARIANT:" at 6097,-434 h60
  text ".VersionControl_RevNumber" at 1035.5,-656.17 h60
  text "SVN REV:" at 1541.5,-656.17 h60
  text ".PCB_Rev" at 2088,-656.17 h60
  text "REV:" at 2379.5,-656.17 h60
  text ".PRJ_Number" at 3224,-656.17 h60
  text "BOARD #:" at 3769.5,-656.17 h60
  text "PCB VIEWED FROM BOTTOM SIDE" at 6246,-656.17 h60
  text ".TID" at 3224,-859.5 h60
  text "TID #:" at 3769.5,-859.5 h60
  text "TEXAS INSTRUMENTS" at 904.5,-1064.84 h60
  text ".Print_Time" at 2169,-1064.84 h60
  text ".Print_Date" at 2898,-1064.84 h60
  text "GENERATED    :" at 3767.5,-1064.84 h60
  text ".plot_File_Name" at 5440.5,-1064.84 h60
  text "PLOT NAME =" at 6246,-1064.84 h60
M9 Title Sheet:
  drawing of 57 lines, arcs and shapes, not listed
  text "1" at 739.84,8036.5 h70
  text "2" at 3235.5,8036.5 h70
  text "3" at 5724.84,8036.5 h70
  text "4" at 8231.51,8036.5 h70
  text "5" at 10730.5,8036.5 h70
  text "6" at 13235.5,8036.5 h70
  text "A" at -416.5,6893.5 h70
  text "A" at 14383.5,6893.5 h70
  text "B" at -416.5,4513.5 h70
  text "B" at 14383.5,4513.5 h70
  text "C" at -416.5,2138.5 h70
  text "C" at 14383.5,2138.5 h70
  text "PROJECT TITLE:" at 11343.5,277.5 h45
  text ".PRJ_Title" at 11393.5,144.17 h70
  text "DESIGNED FOR:" at 11343.5,-23.5 h45
  text ".PRJ_Customer" at 11393.5,-163.5 h70
  text "D" at -416.5,-231.5 h70
  text "D" at 14383.5,-231.5 h70
  text "FILE NAME:" at 11343.5,-323.5 h45
  text ".PCB_File_Name_No_Path" at 11393.5,-443.5 h70
  text "Texas Instruments (TI) and/or its licensors do not warrant the accuracy or completeness of this specification" at 6374,-605.34 h45
  text "ENGINEER:" at 11343.5,-613.5 h45
  text "LAYOUT BY:" at 12848.5,-613.5 h45
  text "or any information contained therein. TI and/or its licensors do not warrant that this design will meet" at 6329.01,-718 h45
  text ".PRJ_Engineer" at 11393.5,-768.49 h70
  text ".PCB_Layout" at 12899,-768.49 h70
  text "the specifications, will be suitable for your application or fit for any particular purpose, or will operate in" at 6329.01,-830.67 h45
  text ".Layer_Name" at 577,-858.49 h60
  text "ALTIUM DESIGNER VERSION:" at 12848.5,-923.5 h45
  text "an implementation. TI and/or its licensors do not warrant that the design is production worthy. You should" at 6329.01,-943.33 h45
  text "completely validate and test your design implementation to confirm the system functionality for your application." at 6374,-1056 h45
  text ".print_Scale" at 11393.5,-1056.83 h70
  text ".Application_BuildNumber" at 12899,-1056.83 h70
  text "1" at 739.84,-1263.5 h70
  text "2" at 3235.5,-1263.5 h70
  text "3" at 5724.84,-1263.5 h70
  text "4" at 8231.51,-1263.5 h70
  text "5" at 10730.5,-1263.5 h70
  text "6" at 13235.5,-1263.5 h70
M10 Fab Notes:
  drawing of 189 lines, arcs and shapes, not listed
  text "DESIGN INFORMATION" at 12382.02,6356.17 h60
  text "MIN. TRACK WIDTH:" at 11737.46,6224.05 h60
  text "8" at 12833.7,6224.05 h60
  text "MIL" at 12988.46,6224.05 h60
  text "7.874" at 12667.32,6102.36 h60
  text "MIN. CLEARANCE:" at 11737.46,6099.92 h60
  text "MIL" at 12988.46,6099.92 h60
  text "19.685" at 12628,5977 h60
  text "MIN. VIA PAD SIZE:" at 11737.46,5975.8 h60
  text "MIL" at 12988.46,5975.8 h60
  text "0.05mm (2MIL)" at 12432.46,5845.9 h60
  text "MINIMUM ANNULAR RING" at 11408.23,5837.67 h60
  text "EXTERNAL" at 13140.46,5837.67 h60
  text "PER" at 11608.23,5727.55 h60
  text "IPC-D-275 CLASS 2 LEVEL C" at 11828.23,5727.54 h60
  text "MIL, HOLES" at 13316.46,5627.07 h60
  text "+/-" at 12924,5618.48 h60
  text "+/-" at 13778,5618.48 h60
  text "REGISTRATION TOLERANCES:" at 11408.23,5617.42 h60
  text "METAL" at 12608,5617.42 h60
  text "5" at 13184.2,5617.42 h60
  text "3" at 14017.2,5617.42 h60
  text "MIL" at 14133.46,5617.42 h60
  text "HOLE SIZE TOLERANCE (UNLESS OTHERWISE SPECIFIED):" at 11408.23,5519.1 h60
  text "+/-" at 13778,5516.23 h60
  text "3" at 14017.2,5515.17 h60
  text "MIL" at 14133.46,5515.17 h60
  text "MATERIAL:" at 11333.46,5377.52 h60
  text "FR-4 High Tg" at 12319.9,5249 h60
  text "X" at 12175.46,5241.01 h60
  text "FR-408" at 11754.46,5236.49 h60
  text "OTHER" at 13242.46,5236.49 h60
  text "62 MIL (1.6mm) +/-10%" at 12074.56,5093.46 h60
  text "X" at 11954.46,5091.01 h60
  text "THICKNESS:" at 11408.23,5085.24 h60
  text "OTHER" at 13359.46,5085.24 h60
  text "TOLERANCE:" at 11408.23,4946.92 h60
  text "X" at 12256.46,4946.92 h60
  text "ANSI IPC-6012 TYPE 3 CLASS 2" at 12434.48,4946.92 h60
  text "OTHER +/-" at 12434.46,4802.73 h60
  text "BOW & TWIST:" at 11408.23,4657.54 h60
  text "X" at 12256.46,4657.54 h60
  text "ANSI IPC-6012 TYPE 3 CLASS 2" at 12434.48,4657.54 h60
  text "OTHER +/-" at 12434.46,4510.85 h60
  text "DRILLING:" at 11333.46,4380.23 h60
  text "NC_DRILL FILES" at 13094.46,4275.04 h60
  text "REFERENCE:" at 11408.23,4271.1 h60
  text "X" at 12065.46,4271.01 h60
  text "AS SHOWN" at 12243.46,4271.1 h60
  text "X" at 12966.46,4271.1 h60
  text "OTHER" at 13392.46,4128.85 h60
  text "PTH COPPER THICKNESS:" at 11407.91,4125.32 h60
  text "X" at 12547.14,4125.32 h60
  text "20-30 um" at 12675.14,4125.32 h60
  text "BOARD FINISH:" at 11333.46,3977.73 h60
  text "SILKSCREEN:" at 11488.68,3867.6 h60
  text "X" at 12446.46,3867.6 h60
  text "TOP" at 12563.46,3867.6 h60
  text "X" at 12956.46,3867.6 h60
  text "BOTTOM" at 13074.46,3867.6 h60
  text "SILKSCREEN COLOR:" at 11488.68,3712.41 h60
  text "X" at 12445.46,3712.41 h60
  text "WHITE" at 12563.46,3712.41 h60
  text "OTHER" at 13074.46,3712.41 h60
  text "X" at 12576.46,3568.96 h60
  text "GREEN" at 12694.46,3568.96 h60
  text "OTHER" at 13312.46,3568.96 h60
  text "SOLDER RESIST COLOR:" at 11488.68,3562.1 h60
  text "X" at 12576.46,3414.71 h60
  text "MATTE" at 12694.46,3414.71 h60
  text "SEMI-GLOSS" at 13312,3414.07 h60
  text "IMMERSION GOLD (ENIG)" at 12394.46,3241.94 h60
  text "ENEPIG" at 13732,3234.72 h60
  text "SURFACE FINISH:" at 11333.46,3233.72 h60
  text "X" at 12216.46,3233.72 h60
  text "IMM. TIN/SILVER OR EQUIV" at 11663,3096.4 h60
  text "OTHER" at 13094.46,3092.47 h60
  text "ARRAY/PANEL:" at 11333.46,2937.09 h60
  text "CUT AND TRIM PER M1 BOARD OUTLINE" at 12394.46,2928.87 h60
  text "N.C. ROUTE" at 12394.46,2792.9 h60
  text "X" at 13082.46,2792.9 h60
  text "V. SCORE" at 13260.46,2792.9 h60
  text "CERTIFICATION:" at 11333.46,2663.77 h60
  text "MATERIALS AND WORKMANSHIP FOR ALL PCBS" at 12058.46,2663.77 h60
  text "TO MEET OR EXCEED THE REQUIREMENTS OF:" at 12058.46,2569.71 h60
  text "X" at 11695.97,2441.08 h60
  text "ANSI IPC-A-600F CLASS ->" at 11823.96,2441.08 h60
  text "X" at 13471.97,2441.08 h60
  text "2" at 13581.96,2441.08 h60
  text "1" at 13266.96,2439.58 h60
  text "3" at 13935.96,2439.58 h60
  text "X" at 12507.97,2293.39 h60
  text "RoHS" at 12635.96,2293.39 h60
  text "OTHER" at 13280.36,2293.39 h60
  text "PER ORDER" at 13677.42,2293.39 h60
  text "ALL BOARDS MUST MEET OR EXCEED UL94-V0 REQUIREMENTS." at 11361,2139.57 h60
  text "PCB MUST BEAR THE UL94V-0 UL REGISTERED MATERIAL ID NUMBER" at 11361,2023.5 h60
  text "ADDITIONAL REQUIREMENTS:" at 11333.46,1854.08 h60
  text "MICROSECTION:" at 11408.23,1746.95 h60
  text "YES" at 12313.96,1746.95 h60
  text "REQUIRED" at 13175.46,1602.62 h60
  text "BARE BOARD ELEC. TEST:" at 11408.23,1599.76 h60
  text "NONE" at 12713.96,1599.76 h60
  text "X" at 13057.46,1599.76 h60
  text "PER ORDER" at 13767.46,1599.76 h60
  text "X" at 11465.97,1454.39 h60
  text "7.87 MIL VIAS REQUIRE NON-CONDUCTIVE FILL AND PLANARIZE" at 11576.38,1394.82 h56
  text "XX MIL VIAS REQUIRE CONDUCTIVE FILL AND PLANARIZE" at 11584.38,1290.84 h60
  text "OUTER XX MIL TRACES REQUIRE 50 OHM SINGLE-ENDED IMPEDANCE" at 11583.39,1127.46 h58
  text "LAYER 2 & 3 (INNER LAYERS) XX MIL WIDE, XX MIL SPACE / TRACES REQUIRE 100 OHM DIFFERENTIAL IMPEDANCE" at 11575.39,891.74 h60
  text ".Layer_Name" at 577,-858.49 h60
M11 Gerber Information:
  lines w10: -292,-930.17 6308,-930.17 ; -292,-726.83 6310,-726.83 ; -292,-523.5 -292,-1133.5 3713,-1133.5 6310,-1133.5 6310,-523.5 -291.5,-523.5 -291.5,-1133.5 1284,-1133.5 ; 2173,-1133.5 2173,-523.5 ; 3440,-726.83 3440,-523.5 ; 4280,-726.83 4280,-523.5 ; 4902,-1140 4902,-937.17
  text "ALL ARTWORK VIEWED FROM TOP SIDE" at -228.5,-655.67 h60
  text "BOARD #:" at 2248,-655.67 h60
  text ".PRJ_Number" at 2793.5,-655.67 h60
  text "REV:" at 3638,-655.67 h60
  text ".PCB_Rev" at 3929.5,-655.67 h60
  text "SVN REV:" at 4476,-655.67 h60
  text ".VersionControl_RevNumber" at 4982,-655.67 h60
  text "LAYER NAME =" at -228.5,-858.49 h60
  text "TID #:" at 2248,-859 h60
  text ".TID" at 2793.5,-859 h60
  text "PLOT NAME =" at -228.5,-1064.34 h60
  text ".plot_File_Name" at 577,-1064.34 h60
  text "GENERATED    :" at 2250,-1064.34 h60
  text ".Print_Date" at 3119.5,-1064.34 h60
  text ".Print_Time" at 3848.5,-1064.34 h60
  text "TEXAS INSTRUMENTS" at 5113,-1064.34 h60
M12 Stackup:
  drawing of 295 lines, arcs and shapes, not listed
  text "Layer" at 9821.59,7874.94 h60
  text "Name" at 10231.51,7874.94 h60
  text "Material" at 11171.25,7874.94 h60
  text "Thickness" at 12031.02,7874.94 h60
  text "Constant" at 12680.85,7874.94 h60
  text "Board Layer Stack" at 13250.71,7874.94 h60
  text "Top Overlay" at 10231.51,7754.94 h60
  text "Top Solder" at 10231.51,7634.94 h60
  text "Solder Resist" at 11171.25,7634.94 h60
  text "0.40mil" at 12031.02,7634.94 h60
  text "3.5" at 12680.85,7634.94 h60
  text "1" at 9821.59,7514.94 h60
  text "Top Layer" at 10231.51,7514.94 h60
  text "2.80mil" at 12031.02,7514.94 h60
  text "Dielectric 1" at 10231.51,7394.94 h60
  text "FR-4 High Tg" at 11171.25,7394.94 h60
  text "8.00mil" at 12031.02,7394.94 h60
  text "4.2" at 12680.85,7394.94 h60
  text "2" at 9821.59,7274.94 h60
  text "Signal Layer 1" at 10231.51,7274.94 h60
  text "1.40mil" at 12031.02,7274.94 h60
  text "Dielectric 2" at 10231.51,7154.94 h60
  text "FR-4 High Tg" at 11171.25,7154.94 h60
  text "37.20mil" at 12031.02,7154.94 h60
  text "4.2" at 12680.85,7154.94 h60
  text "3" at 9821.59,7034.94 h60
  text "Signal Layer 2" at 10231.51,7034.94 h60
  text "1.40mil" at 12031.02,7034.94 h60
  text "Dielectric 3" at 10231.51,6914.94 h60
  text "FR-4 High Tg" at 11171.25,6914.94 h60
  text "8.00mil" at 12031.02,6914.94 h60
  text "4.2" at 12680.85,6914.94 h60
  text "4" at 9821.59,6794.94 h60
  text "Bottom Layer" at 10231.51,6794.94 h60
  text "2.80mil" at 12031.02,6794.94 h60
  text "Bottom Solder" at 10231.51,6674.94 h60
  text "Solder Resist" at 11171.25,6674.94 h60
  text "0.40mil" at 12031.02,6674.94 h60
  text "3.5" at 12680.85,6674.94 h60
  text "Bottom Overlay" at 10231.51,6554.94 h60
  text ".Layer_Name" at 577,-858.49 h60
M13 Component Bodies Top:
  text ".Layer_Name" at 577,-858.49 h60
M14 Component Bodies Bottom:
  text ".Layer_Name" at 577,-858.49 h60
M15 Courtyards Top:
  text ".Layer_Name" at 577,-858.49 h60
M16 Courtyards Bottom:
  text ".Layer_Name" at 577,-858.49 h60
Drill Drawing:
  circle w10: c5732.72,2877.48 r16.58
  circle w10: c5732.72,2877.48 r27.63
  circle w10: c5732.72,2255.88 r27.63
  lines w10: 5705.09,1979.62 5760.34,1979.62 5760.34,2034.87 5705.09,2034.87 5705.09,1979.62 ; 5705.09,2117.75 5718.9,2117.75 5718.9,2103.94 5746.53,2103.94 5746.53,2117.75 5760.34,2117.75 5760.34,2145.38 5746.53,2145.38 5746.53,2159.19 5718.9,2159.19 5718.9,2145.38 5705.09,2145.38 5705.09,2117.75 ; 5705.09,2366.39 5718.9,2366.39 5732.72,2352.58 5746.53,2366.39 5760.34,2366.39 5746.53,2380.2 5760.34,2394.02 5746.53,2394.02 5732.72,2407.83 5718.9,2394.02 5705.09,2394.02 5718.9,2380.2 5705.09,2366.39 ; 5705.09,2504.52 5732.72,2476.9 5760.34,2504.52 5732.72,2532.15 5705.09,2504.52 ; 5705.09,2601.22 5732.72,2615.03 5760.34,2601.22 5746.53,2628.84 5760.34,2656.47 5732.72,2642.66 5705.09,2656.47 5718.9,2628.84 5705.09,2601.22 ; 5705.09,2780.79 5760.34,2780.79 5732.72,2725.54 5705.09,2780.79 ; 5705.09,2974.18 5705.09,2987.99 5718.9,3001.8 5705.09,3015.62 5705.09,3029.43 5718.9,3029.43 5732.72,3015.62 5746.53,3029.43 5760.34,3029.43 5760.34,3015.62 5746.53,3001.8 5760.34,2987.99 5760.34,2974.18 5746.53,2974.18 5732.72,2987.99 5718.9,2974.18 5705.09,2974.18 ; 5705.09,3098.5 5760.34,3098.5 5760.34,3153.75 5705.09,3153.75 5705.09,3098.5 ; 5716.14,3109.55 5749.29,3109.55 5749.29,3142.7 5716.14,3142.7 5716.14,3109.55
  lines w12: 5655,1942.32 8840,1942.32 ; 5655,3185.52 8840,3185.52 ; 5992.86,1818 5992.86,3309.84 ; 6322.14,1818 6322.14,3309.84 ; 6914.94,1818 6914.94,3309.84 ; 7174.08,1818 7174.08,3309.84 ; 7549.24,1818 7549.24,3309.84 ; 8273.57,1818 8273.57,3309.84 ; 5655,1818 8840,1818 8840,3309.84 5655,3309.84 5655,1818
  text "Symbol" at 5729.59,3222.82 h72
  text "Count" at 6030.16,3222.82 h72
  text "Hole Size" at 6359.44,3222.82 h72
  text "Plated" at 6952.23,3222.82 h72
  text "Hole Type" at 7211.38,3222.82 h72
  text "Drill Layer Pair" at 7586.53,3222.82 h72
  text "Hole Tolerance" at 8310.86,3222.82 h72
  text "1339" at 6030.16,3098.5 h60
  text "7.87mil (0.200mm)" at 6359.44,3098.5 h60
  text "PTH" at 6952.23,3098.5 h60
  text "Round" at 7211.38,3098.5 h60
  text "Top Layer - Bottom Layer" at 7586.53,3098.5 h60
  text "8" at 6030.16,2974.18 h60
  text "8.00mil (0.203mm)" at 6359.44,2974.18 h60
  text "PTH" at 6952.23,2974.18 h60
  text "Round" at 7211.38,2974.18 h60
  text "Top Layer - Bottom Layer" at 7586.53,2974.18 h60
  text "2" at 6030.16,2849.86 h60
  text "16.00mil (0.406mm)" at 6359.44,2849.86 h60
  text "PTH" at 6952.23,2849.86 h60
  text "Round" at 7211.38,2849.86 h60
  text "Top Layer - Bottom Layer" at 7586.53,2849.86 h60
  text "17" at 6030.16,2725.54 h60
  text "40.00mil (1.016mm)" at 6359.44,2725.54 h60
  text "PTH" at 6952.23,2725.54 h60
  text "Round" at 7211.38,2725.54 h60
  text "Top Layer - Bottom Layer" at 7586.53,2725.54 h60
  text "6" at 6030.16,2601.22 h60
  text "40.16mil (1.020mm)" at 6359.44,2601.22 h60
  text "PTH" at 6952.23,2601.22 h60
  text "Round" at 7211.38,2601.22 h60
  text "Top Layer - Bottom Layer" at 7586.53,2601.22 h60
  text "5" at 6030.16,2476.9 h60
  text "43.31mil (1.100mm)" at 6359.44,2476.9 h60
  text "PTH" at 6952.23,2476.9 h60
  text "Round" at 7211.38,2476.9 h60
  text "Top Layer - Bottom Layer" at 7586.53,2476.9 h60
  text "+/-1.97mil" at 8310.86,2476.9 h60
  text "52" at 6030.16,2352.58 h60
  text "45.28mil (1.150mm)" at 6359.44,2352.58 h60
  text "PTH" at 6952.23,2352.58 h60
  text "Round" at 7211.38,2352.58 h60
  text "Top Layer - Bottom Layer" at 7586.53,2352.58 h60
  text "9" at 6030.16,2228.26 h60
  text "63.00mil (1.600mm)" at 6359.44,2228.26 h60
  text "PTH" at 6952.23,2228.26 h60
  text "Round" at 7211.38,2228.26 h60
  text "Top Layer - Bottom Layer" at 7586.53,2228.26 h60
  text "4" at 6030.16,2103.94 h60
  text "125.98mil (3.200mm)" at 6359.44,2103.94 h60
  text "PTH" at 6952.23,2103.94 h60
  text "Round" at 7211.38,2103.94 h60
  text "Top Layer - Bottom Layer" at 7586.53,2103.94 h60
  text "4" at 6030.16,1979.62 h60
  text "270.00mil (6.858mm)" at 6359.44,1979.62 h60
  text "PTH" at 6952.23,1979.62 h60
  text "Round" at 7211.38,1979.62 h60
  text "Top Layer - Bottom Layer" at 7586.53,1979.62 h60
  text "1446 Total" at 6030.16,1855.3 h60
  text ".Layer_Name" at 577,-858.49 h60
M17 Embedded Cavity:
  text ".Layer_Name" at 577,-858.49 h60
M18 Embedded Assembly:
  text ".Layer_Name" at 577,-858.49 h60
M19 Embedded Keepout:
  text ".Layer_Name" at 577,-858.49 h60

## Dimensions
0,3200 to 0,0 on M2 Board Dimensions
0,0 to 5500,0 on M2 Board Dimensions
0,-400 to 1000,-400 on M2 Board Dimensions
